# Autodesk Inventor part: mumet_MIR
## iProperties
Shininess: 64.0
Length Units: 11272
Angle Units: 11279
Time Units: 11290
Mass Units: 11286
Length Display Precision: 3
Angle Display Precision: 2
Compacted: True
Part Number: mumet_MIR
Document SubType Name: Modeling
Created: 2004-08
Designer: John Blackburn
Material: Default
Manufacturer: Standard
Standards Organization: Custom
Density: 0.0
Volumn: 0.0
Area: 0.0
PropertySet Name: Model Information
Control State: 0
Master: False
Checked Out: False
Author: John Blackburn
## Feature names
1. Derived Body1 [Tagging]
